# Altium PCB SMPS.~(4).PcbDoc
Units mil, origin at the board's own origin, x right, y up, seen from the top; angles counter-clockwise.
Board outline 3937.01 x 3149.61 mil, 2 copper layers (Top Layer, Bottom Layer); 87 components, 38 nets, 260 pads, 271 vias.
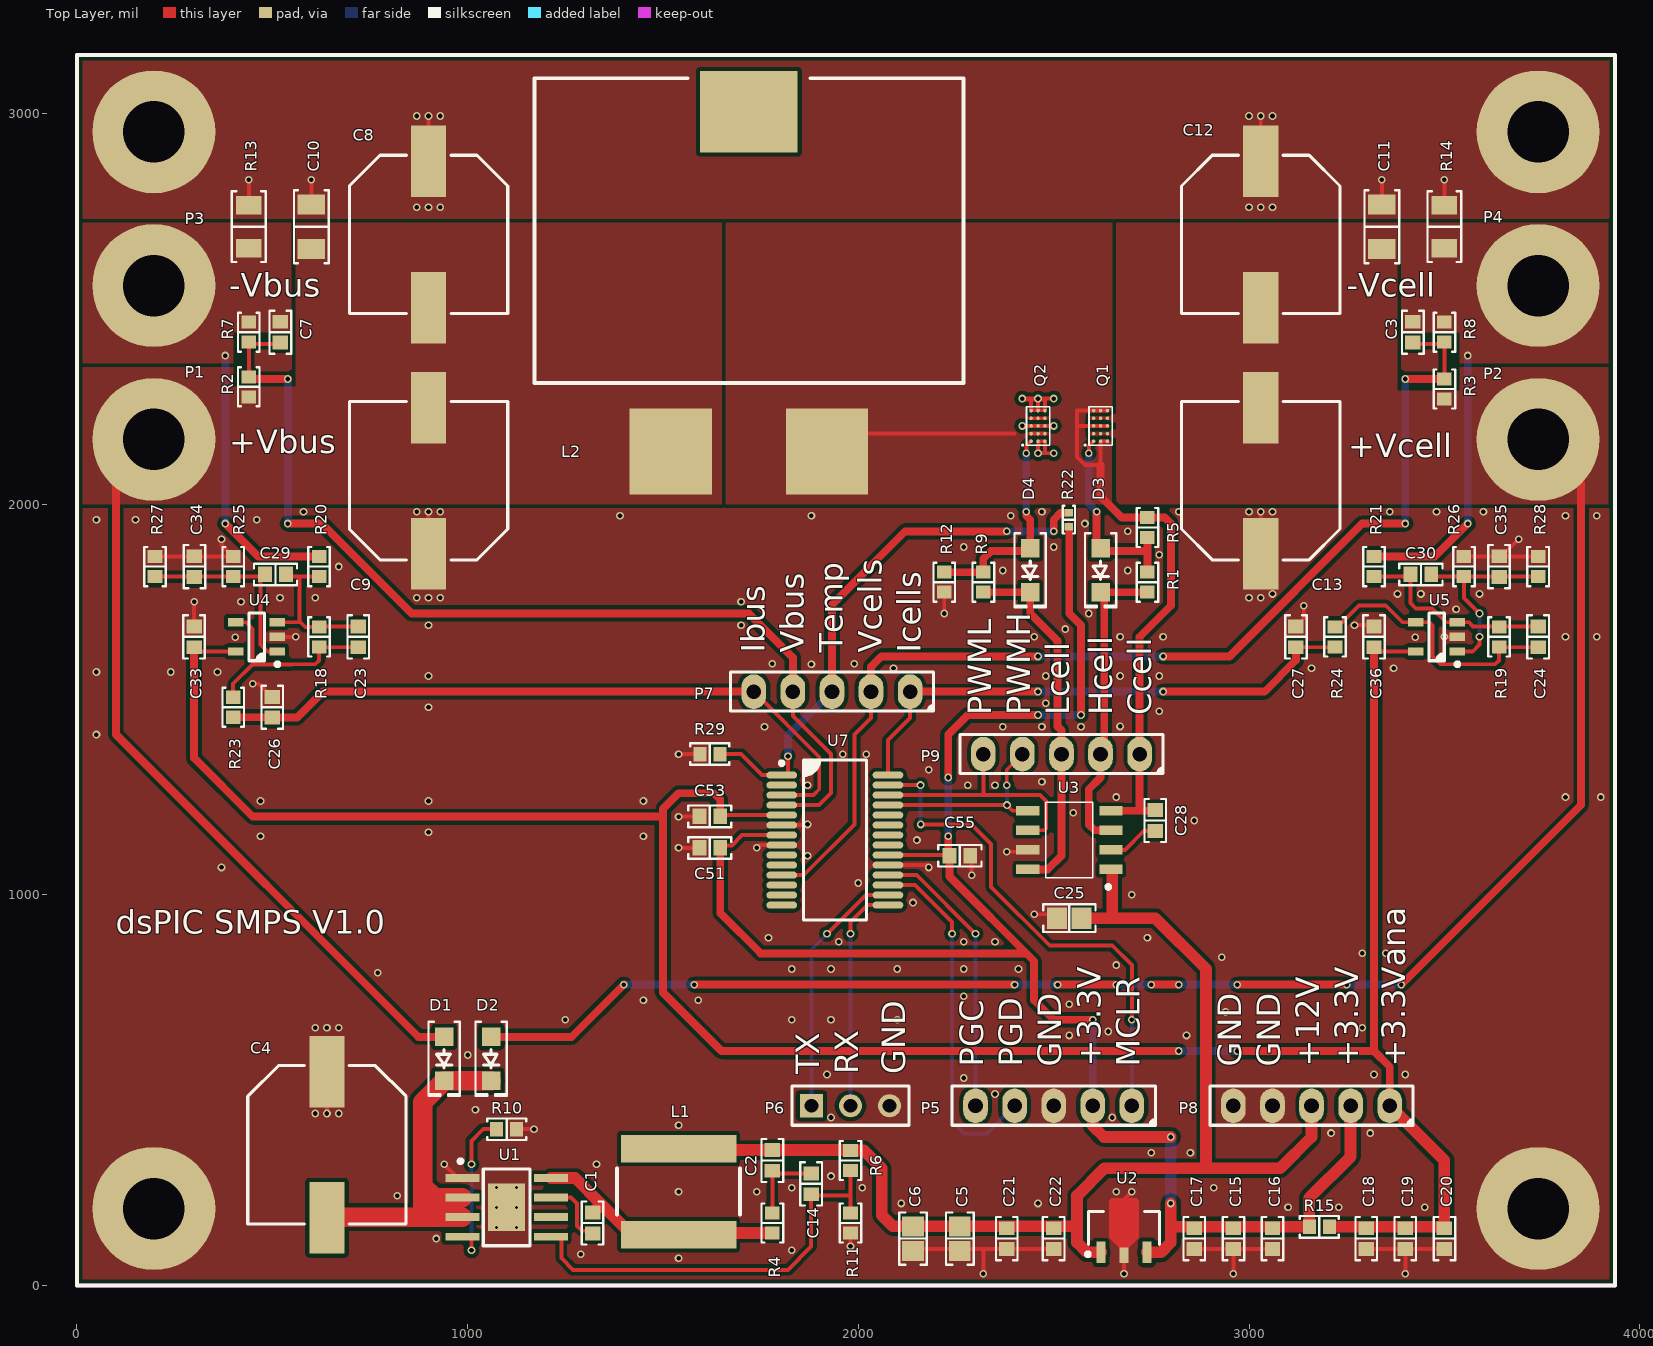
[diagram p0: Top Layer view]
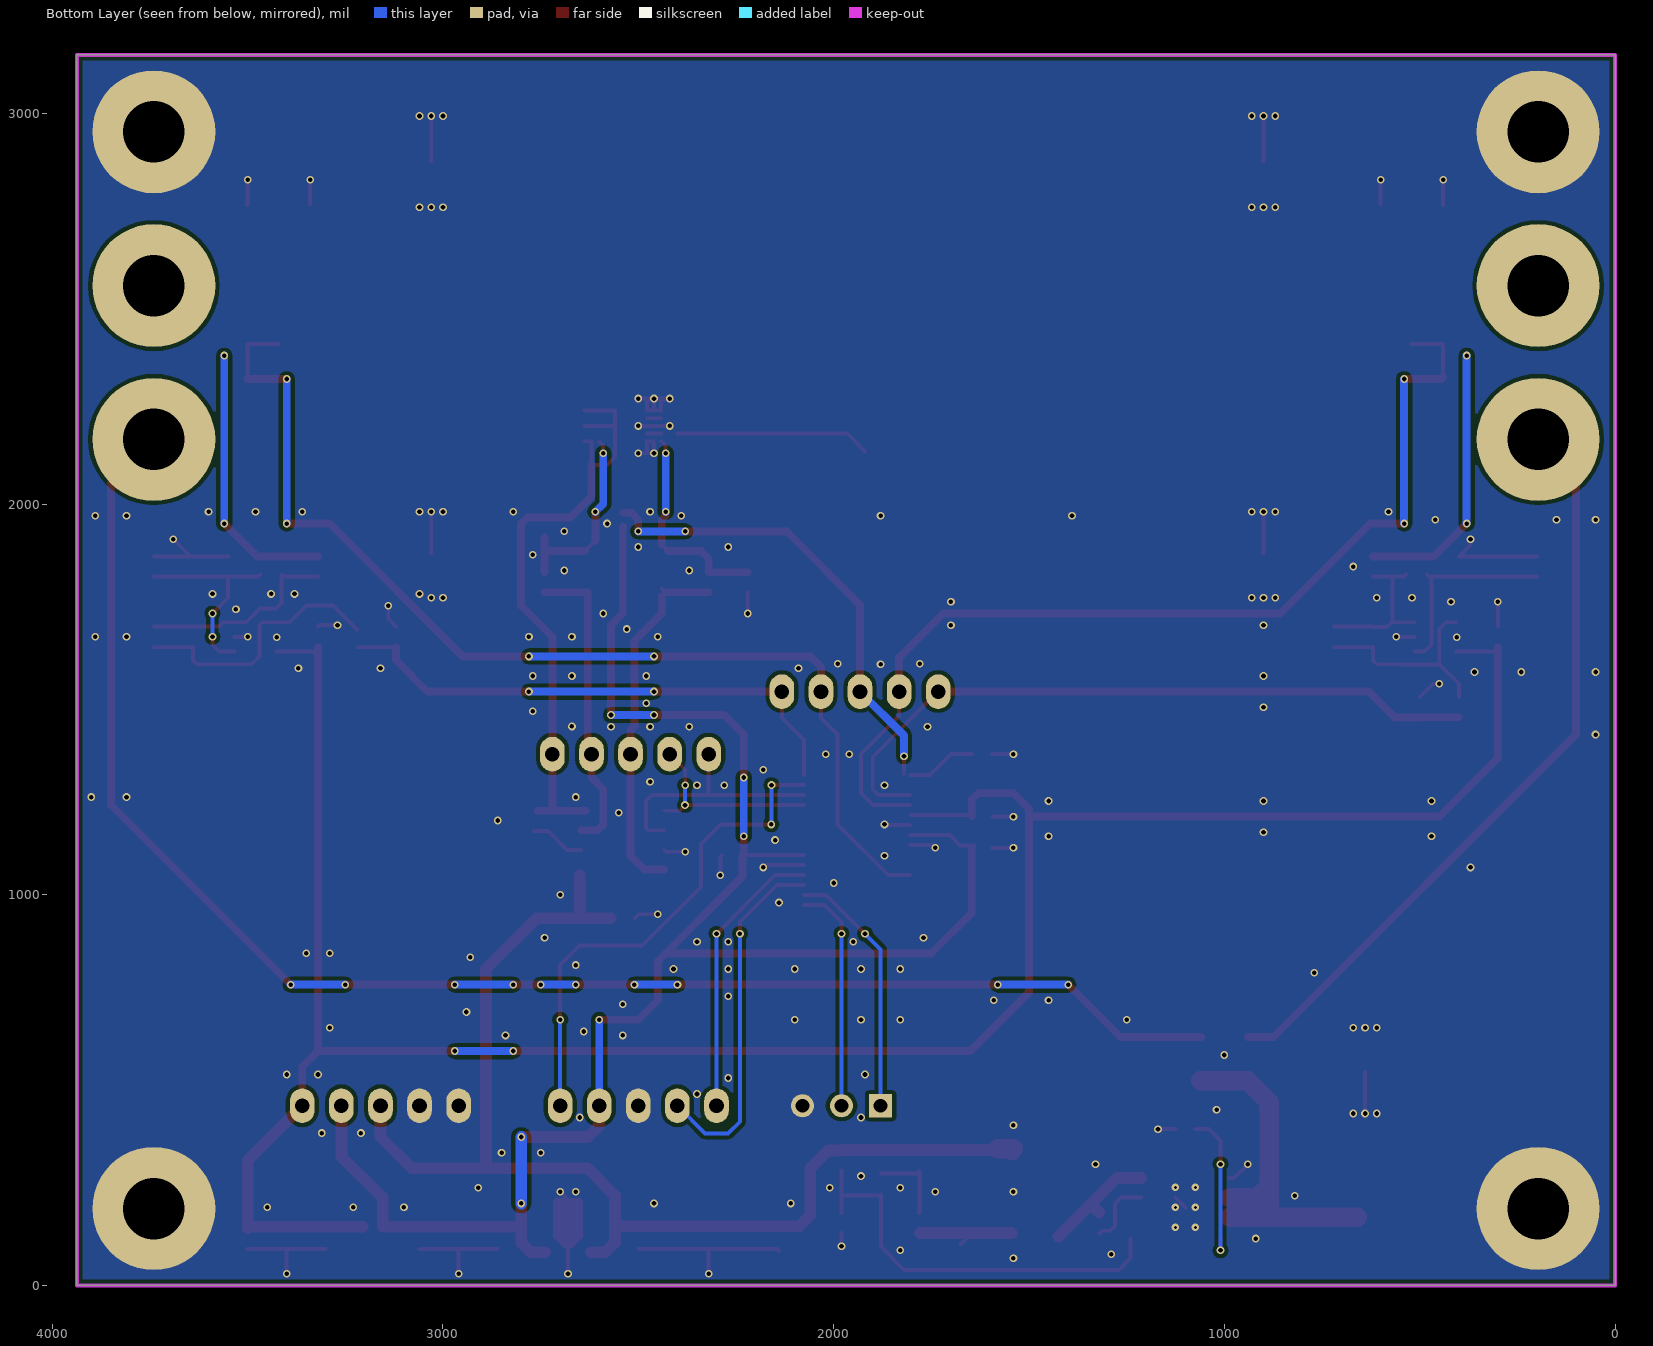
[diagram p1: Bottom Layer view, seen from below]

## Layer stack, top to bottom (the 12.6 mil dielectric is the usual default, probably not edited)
Top Solder: solder mask 0.4, Solder Resist, Dk 3.5
Top Layer: signal copper 1.4
Dielectric 1: dielectric 12.6, FR-4, Dk 4.8
Bottom Layer: signal copper 1.4
Bottom Solder: solder mask 0.4, Solder Resist, Dk 3.5

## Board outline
0,0 0,3149.61 3937.01,3149.61 3937.01,0

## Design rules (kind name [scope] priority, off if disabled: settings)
Clearance [All] p1: gap=10 ignorepadtopadclearanceinfootprint=FALSE except(0: Arc-Hole Track-Hole SMDPad-Hole THPad-Hole Via-Hole Fill-Hole Poly-Hole Region-Hole Text-Hole; 7: SMDPad-SMDPad; 8: Track-SMDPad; 9: Arc-Arc Arc-Track Arc-SMDPad Track-Track; 20: THPad-THPad)
ComponentClearance U1 [InComponent('U1')] p1: gap=20 collisioncheckmode=3 verticalgap=0 showdistances=TRUE
ComponentClearance [All] p2: gap=19.68 collisioncheckmode=3 verticalgap=3.94 showdistances=TRUE
Height [All] p1: minheight=0 maxheight=2000 prefheight=500
HoleSize [All] p1: absolutevalues=TRUE maxlimit=393.7 minlimit=7.87 maxpercent=80.000 minpercent=20.000
MinimumSolderMaskSliver [All] p1: minsoldermaskwidth=1
PlaneClearance [All] p1: clearance=10
PlaneConnect [All] p1: planeconnectstyle=Direct reliefexpansion=20 reliefentries=4 reliefconductorwidth=20 reliefairgap=20
PolygonConnect GND [InNet('GND')] p1: connectstyle=Direct reliefconductorwidth=10 reliefentries=4 polygonreliefangle="90 Angle" airgapwidth=10
PolygonConnect DirectConnect [All] p2: connectstyle=Direct reliefconductorwidth=10 reliefentries=4 polygonreliefangle="90 Angle" airgapwidth=10
RoutingVias [All] p1: holewidth=7.87 width=31.5 viastyle="Through Hole" minholewidth=7.87 minwidth=15.75 maxholewidth=15.75 maxwidth=31.5
SilkToSilkClearance [All] p1: silktosilkclearance=0
SolderMaskExpansion [All] p1: expansion=4
Width [All] p1: maxlimit=500 minlimit=10 preferedwidth=10
23 further rules are at their usual default settings.

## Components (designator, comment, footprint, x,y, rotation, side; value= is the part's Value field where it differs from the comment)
C1 "10nF" C0603 1320,160 r270 top
C2 "1nF" C0603 1780,320 r90 top
C3 "10nF" C0603 3419.28,2440 r270 top
C4 "47µF 80V" "CAP ALUM 10.3MM" 640,360 r270 top
C5 "10µF 16V" C0805 2260,120 r270 top
C6 "10µF 16V" C0805 2140,120 r270 top
C7 "10nF" C0603 520.72,2440 r270 top
C8 "47µF 80V" "CAP ALUM 10.3MM" 900,2690 r270 top
C9 "47µF 80V" "CAP ALUM 10.3MM" 900,2060 r90 top
C10 "1µF 80V" C1206 600,2710 r270 top
C11 "1µF 80V" C1206 3340,2710 r270 top
C12 "47µF 80V" "CAP ALUM 10.3MM" 3030,2690 r270 top
C13 "47µF 80V" "CAP ALUM 10.3MM" 3030,2060 r90 top
C14 "47pF" C0603 1879.28,260 r90 top
C15 "10µF" C0603 2960,120 r270 top
C16 "100nF" C0603 3060,120 r270 top
C17 "10nF" C0603 2860,120 r270 top
C18 "10µF" C0603 3300,120 r270 top
C19 "100nF" C0603 3400,120 r270 top
C20 "10nF" C0603 3500,120 r270 top
C21 "100nF" C0603 2380,120 r270 top
C22 "1µF 16V" C0603 2500,120 r270 top
C23 "22pF" C0603 720,1660 r90 top
C24 "22pF" C0603 3740,1660 r270 top
C25 "10µF 16V" C0805 2540,940 r0 top
C26 "33pF" C0603 500,1480 r270 top
C27 "33pF" C0603 3120,1660 r270 top
C28 "1µF 16V" C0603 2760,1190 r270 top
C29 "22pF" C0603 508.28,1820 r0 top
C30 "22pF" C0603 3440,1820 r180 top
C33 "100nF" C0603 300,1660 r90 top
C34 "22pF" C0603 300.72,1840 r270 top
C35 "22pF" C0603 3640,1840 r270 top
C36 "100nF" C0603 3320,1660 r90 top
C51 "100nF" C0603 1620,1120 r0 top
C53 "100nF" C0603 1620,1200.72 r0 top
C55 "100nF" C0603 2260,1100 r180 top
D1 "DSS120UTR" SOD123F 940,580 r270 top
D2 "DSS120UTR" SOD123F 1060,580 r270 top
D3 "DSS120UTR" SOD123F 2620,1830 r270 top
D4 "DSS120UTR" SOD123F 2440,1830 r270 top
L1 "NR8040T220M" SELF_SMD_8x8 1540,240 r90 top
L2 "PQ2614BHA-150K" SELF_SMD_PQ2617 1720,2700 r0 top
P1 "PTH" HOLE_4#1 196.85,2165.35 r0 top
P2 "PTH" HOLE_4#1 3740.16,2165.35 r0 top
P3 "PTH" HOLE_4#2 196.85,2547.38 r0 top
P4 "PTH" HOLE_4#1 3740.16,2559.06 r0 top
P5 "5x2.54" "SAMTEC SSW-105-03-T-S" 2500,460 r180 top
P6 "3x2.54" HDR1X3 1880,460 r0 top
P7 "5x2.54" "SAMTEC SSW-105-03-T-S" 1932.59,1520 r180 top
P8 "5x2.54" "SAMTEC SSW-105-03-T-S" 3160,460 r180 top
P9 "5x2.54" "SAMTEC SSW-105-03-T-S" 2520,1360 r180 top
Q1 "EPC2045" EPC2045 2620,2200 r90 top
Q2 "EPC2045" EPC2045 2460,2200 r90 top
R1 "5R11" R0603 2740,1800 r90 top
R2 "21.5k 0.1%" R0603 440,2300 r90 top
R3 "21.5k 0.1%" R0603 3500,2294.41 r90 top
R4 "249k" R0603 1780,160 r90 top
R5 "10k" R0603 2740,1940 r90 top
R6 "91k" R0603 1980,320 r270 top
R7 "1k 0.1%" R0603 440,2440 r90 top
R8 "1k 0.1%" R0603 3500,2440 r90 top
R9 "5R11" R0603 2320,1800 r90 top
R10 "30.1k" R0603 1100,400 r0 top
R11 "10k" R0603 1980,160 r270 top
R12 "10k" R0603 2220,1800 r270 top
R13 "5m 1% 1W 50ppm" R1206 440,2710 r270 top
R14 "5m 1% 1W 50ppm" R1206 3500,2710 r90 top
R15 "1R" R0603 3180,150 r180 top
R18 "100k 0.1%" R0603 620,1660 r270 top
R19 "100k 0.1%" R0603 3640,1660 r90 top
R20 "1k 0.1%" R0603 620,1840 r270 top
R21 "1k 0.1%" R0603 3320,1840 r90 top
R22 "10k CTN" "NTC 0402/1005" 2538.65,1960 r270 top
R23 "1k" R0603 400,1480 r270 top
R24 "1k" R0603 3220,1660 r90 top
R25 "1k 0.1%" R0603 400,1840 r270 top
R26 "1k 0.1%" R0603 3550,1840 r90 top
R27 "100k 0.1%" R0603 200,1840 r90 top
R28 "100k 0.1%" R0603 3740,1840 r90 top
R29 "10k" R0603 1620,1360 r180 top
U1 "LM5164" R-PDSO-G8 1100,200 r270 top
U2 "AP7381-33Y-13" "ON SEMI SOT-89 H" 2680,140 r90 top
U3 "MIC4605-1YM" SOIC-8 2540,1140 r180 top
U4 "LMR321G" "TI SOT-23-5 DBV" 460,1660 r180 top
U5 "LMR321G" "TI SOT-23-5 DBV" 3480,1660 r180 top
U7 "dsPIC33CK256MP202" "CYPRESS SSOP-28 210MIL" 1940,1140 r0 top

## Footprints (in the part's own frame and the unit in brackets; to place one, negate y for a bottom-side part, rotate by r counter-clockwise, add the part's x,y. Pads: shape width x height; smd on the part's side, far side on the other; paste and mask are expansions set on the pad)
C0603 [mm] "Chip Capacitor, 2-Leads, Body 1.60x0.80mm, IPC Medium Density"
  rect 0.9x1 smd: 1(-0.675,0) 2(0.675,0)
  silkscreen extent -1.4,-0.7 1.4,0.7, body extent -0.8,-0.41 0.8,0.41, height 0.82
C0805 [mm] "Chip Capacitor, 2-Leads, Body 2.00x1.20mm, IPC Medium Density"
  rect 1.3x1.4 smd: 1(-0.8,0) 2(0.8,0)
  silkscreen extent -1.7,-0.9 1.7,0.9, body extent -1,-0.64 1,0.64, height 1.26
C1206 [mm] "Chip Capacitor, 2-Leads, Body 3.25x1.60mm, IPC Medium Density"
  rect 1.3x1.8 smd: 1(-1.45,0) 2(1.45,0)
  silkscreen extent -2.37,-1.12 2.37,1.12, body extent -1.6,-0.81 1.6,0.81, height 1.62
"CAP ALUM 10.3MM" [mm] "Aluminum Electrolytic Capacitor, Body 10.30x10.30x10.50mm, IPC Low Density"
  rect 4.65x2.3 smd: 1(-4.75,0) 2(4.75,0)
  silkscreen extent -5.15,-5.15 5.15,5.15, body extent -5.8,-5.15 5.8,5.15, height 10.5
"CYPRESS SSOP-28 210MIL" [mm] "SOP, 28-Leads, Body 10.2x5.3mm, Pitch 0.65mm, IPC Medium Density"
  oval 2x0.45 smd: 1(-3.45,4.225) 2(-3.45,3.575) 3(-3.45,2.925) 4(-3.45,2.275) 5(-3.45,1.625) 6(-3.45,0.975) 7(-3.45,0.325) 8(-3.45,-0.325) 9(-3.45,-0.975) 10(-3.45,-1.625) 11(-3.45,-2.275) 12(-3.45,-2.925) 13(-3.45,-3.575) 14(-3.45,-4.225) 15(3.45,-4.225) 16(3.45,-3.575) 17(3.45,-2.925) 18(3.45,-2.275) 19(3.45,-1.625) 20(3.45,-0.975) 21(3.45,-0.325) 22(3.45,0.325) 23(3.45,0.975) 24(3.45,1.625) 25(3.45,2.275) 26(3.45,2.925) 27(3.45,3.575) 28(3.45,4.225)
  silkscreen extent -3.57,-5.2 2.05,5.2, body extent -3.91,-5.1 3.91,5.1, height 1.97
EPC2045 [mm] "EPC2045 GaNFet"
  round 0.23 smd: 1(-1,0.45) 2(-1,-0.45) 2(-1,0) 2(0,0) 2(0,0.45) 2(0,-0.45) 2(1,-0.45) 2(1,0) 2(1,0.45) 3(-0.5,-0.45) 3(-0.5,0) 3(-0.5,0.45) 3(0.5,-0.45) 3(0.5,0) 3(0.5,0.45)
  silkscreen extent -1.3,-0.75 1.25,1.05, body extent -1.25,-0.75 1.25,0.75, height 0.68
HDR1X3 [mm] "Connector; Header; 3 Position"
  rect 1.5x1.5 hole 0.9: 1(0,0)
  round 1.5 hole 0.9: 2(2.54,0) 3(5.08,0)
  silkscreen extent -1.27,-1.27 6.35,1.27
HOLE_4#1 [mm] "Hole for M4 screw"
  round 8 hole 4: 1(0,0)
HOLE_4#2 [mm] "Hole for M4 screw"
  round 8 hole 4: 1(0,0.297)
"NTC 0402/1005" [mm] "Chip Thermistor, 2-Leads, Body 1.00x0.50mm, IPC Medium Density"
  rect 0.5x0.55 smd: 1(-0.45,0) 2(0.45,0)
  silkscreen extent -0.9,-0.4 0.9,0.4, body extent -0.5,-0.26 0.5,0.26, height 0.52
"ON SEMI SOT-89 H" [mm] "SOT89, 3-Leads, Body 4.50x2.50mm, Pitch 1.50mm, Lead Span 3.3mm, IPC Medium Density"
  rect 1.4x0.6 smd: 1(-1.4,1.5) 3(-1.4,-1.5)
  rect 1x0.6 smd: 2(-1.6,0)
  Top Layer region: -1.1,0.3 -0.45,0.95 1.975,0.95 2.1,0.825 2.1,-0.825 1.975,-0.95 -0.45,-0.95 -1.1,-0.3
  silkscreen extent -1.65,-2.3 1.25,2.47, body extent -2.05,-2.25 2.1,2.25, height 1.5
R0603 [mm] "Chip Resistor, 2-Leads, Body 1.60x0.80mm, IPC Medium Density"
  rect 0.85x0.95 smd: 1(-0.65,0) 2(0.65,0)
  silkscreen extent -1.27,-0.7 1.27,0.7, body extent -0.8,-0.4 0.8,0.4, height 0.45
R1206 [mm] "Chip Resistor, 2-Leads, Body 3.13x1.55mm, IPC Medium Density"
  rect 1.2x1.65 smd: 1(-1.4,0) 2(1.4,0)
  silkscreen extent -2.3,-1.1 2.3,1.1, body extent -1.57,-0.8 1.62,0.8, height 0.6
R-PDSO-G8 [mm] "SOIC, 8-Leads, Body 4,90x3,90mm, Pitch 1,27mm, Thermal Pad 3,10x2,40mm, IPC Medium Density"
  rect 0.5x2.2 smd: 1(-1.905,-2.875) 2(-0.635,-2.875) 3(0.635,-2.875) 4(1.905,-2.875) 5(1.905,2.875) 6(0.635,2.875) 7(-0.635,2.875) 8(-1.905,2.875)
  rect 3.1x2.4 smd paste+0: 9(0,0)
  silkscreen extent -3.12,-3.12 2.5,1.52, body extent -2.5,-2 2.5,2, height 1.7
"SAMTEC SSW-105-03-T-S" [mm]
  oval 1.6x2.25 hole 0.95: 1(-5.08,0) 2(-2.54,0) 3(0,0) 4(2.54,0) 5(5.08,0)
  silkscreen extent -6.61,-1.27 6.61,1.27, body extent -6.6,-1.21 6.6,1.21, height 8.51
SELF_SMD_8x8 [mm] "Self SMD 8x8mm"
  rect 1.8x7.5 smd: 1(-2.8,0) 2(2.8,0)
  silkscreen extent -1.5,-4 1.5,4, body extent -4,-4 4,4, height 3
SELF_SMD_PQ2617 [mil] "Bourns shielded power inductor PQ2617"
  rect 210x220 smd: 1(-200,-565) 2(200,-565)
  rect 250x208 smd: 3(0,304)
  silkscreen extent -549,-390 549,390, body extent -549,-433 549,433, height 748
SOD123F [mm] "SODFL, 2-Leads, Body 1.60x3.50mm, IPC Medium Density"
  rect 1.2x1.2 smd: 1(-1.43,0) 2(1.43,0)
  silkscreen extent -2.41,-1.02 2.41,1.02, body extent -1.75,-0.8 1.75,0.8, height 1.1
SOIC-8 [mm] "8-Pin Plastic Narrow Body Small Outline Integrated Circuit 1.27 mm Pitch, IPC Medium Density"
  rect 1.5x0.6 smd: 1(-2.7,1.905) 2(-2.7,0.635) 3(-2.7,-0.635) 4(-2.7,-1.905) 5(2.7,-1.905) 6(2.7,-0.635) 7(2.7,0.635) 8(2.7,1.905)
  silkscreen extent -2.67,-2.45 1.52,3.17, body extent -1.95,-2.45 1.95,2.45, height 1.76
"TI SOT-23-5 DBV" [mm] "SOT23, 5-Leads, Body 2.90x2.80mm, Pitch 0.95mm, IPC Medium Density"
  rect 1x0.55 smd: 1(-1.35,0.95) 2(-1.35,0) 3(-1.35,-0.95) 4(1.35,-0.95) 5(1.35,0.95)
  silkscreen extent -1.48,-1.55 0.5,1.9, body extent -1.44,-1.43 1.39,1.48, height 1.5

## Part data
C1 C2 C3 C4 C5 C6 C7 C8 C9 C10 C11 C12 C13 C14 C15 C16 C17 C18 C19 C20 C21 C22 C23 C24 C25 C26 C27 C28 C29 C30 C33 C34 C35 C36 C51 C53 C55: library part Cap, "Capacitor"
D1 D2 D3 D4: library part "D Schottky", "Schottky Diode"
L1 L2: library part "Inductor Iron", "Magnetic-Core Inductor"
P1 P2 P3 P4: "Plated Trough Hole for screew"
P5 P7 P8 P9: library part "Header 5", "Header, 5-Pin"
P6: library part "Header 3", "Header, 3-Pin"
Q1 Q2: library part MOSFET_N
R1 R2 R3 R4 R5 R6 R7 R8 R9 R10 R11 R12 R13 R14 R15 R18 R19 R20 R21 R23 R24 R25 R26 R27 R28 R29: library part Res2, "Resistor"
R22: library part "Res Varistor", "Varistor (Voltage-Sensitive Resistor)"
U1: "100-V Input, 1-A synchronous buck DC/DC converter with ultra-low IQ"
U2: library part "Volt Reg", "Voltage Regulator"
U3: "85V Half-Bridge MOSFET Driver with Adaptive Dead Time  and Shoot-Through Protection"
U4 U5: library part "AOP - 1"

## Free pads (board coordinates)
  round 314.96 hole 157.48: 1(196.85,196.85) 1(196.85,2952.76) 1(3740.16,196.85) 1(3740.16,2952.76)

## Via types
v1: diameter 19.68, hole 11.81, Top Layer to Bottom Layer, 265 vias
v2: diameter 19.68, hole 7.87, Top Layer to Bottom Layer, 6 vias

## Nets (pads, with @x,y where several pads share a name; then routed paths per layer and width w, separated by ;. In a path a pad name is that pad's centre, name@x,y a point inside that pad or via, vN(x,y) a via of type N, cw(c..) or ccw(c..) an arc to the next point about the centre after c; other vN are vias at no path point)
+3.3V: C15.1 C16.1 C17.1 C51.2 C55.2 P5.2 P8.2 R15.2 R22.2 U2.3 U7.7 U7.20 | length 4669.4
  Top Layer w10: C51.2@1640,1126.57 1676.57,1126.57 1702.8,1152.8 U7.7 ; U7.20 2224.96,1101.61 2233.43,1093.15 C55.2@2240,1086.57
  Top Layer w20: C51.2 1646.57,953.43 1750,850 2430,850 ; v1(2230,1150) 2230,1103.43 C55.2 2233.43,1093.15 2233.43,1046.57 2450,830 2450,730 2500,680 v1(2600,680) ; v1(2230,1300) 2230,1410 2280,1460 v1(2460,1460) ; R22.2 2540,1940.94 2540,1720 2570,1690 v1(2570,1460)
  Top Layer w25: C17.1 C17.1@2863.43,150
  Top Layer w30: P5.2 2600,408.82 2628.82,380 v1(2800,380) ; U2.3 2774.88,84.88 2800,110 v1(2800,210) ; 2804.17,150 2863.43,150 R15.2 3154.41,224.41 3260,330 P8.2
  Bottom Layer w20: v1(2230,1150) v1(2230,1300) ; v1(2460,1460) v1(2570,1460) ; P5.2 v1(2600,680)
  Bottom Layer w30: v1(2800,210) v1(2800,380)
+3.3Vana: C18.1 C19.1 C20.1 C33.1 C36.1 C53.2 P8.1 R15.1 U4.5 U5.5 U7.5 | length 6358.4
  Top Layer w10: C33.1 310.83,1622.6 U4.5 ; C53.2@1640,1213.43 1646.57,1206.85 1649.45,1203.98 U7.5 ; C36.1 3330.83,1622.6 U5.5
  Top Layer w20: C33.1 300,1350 450,1200 1500,1200 ; C53.2 1646.57,1206.85 1646.57,1243.43 1630,1260 1540,1260 1500,1220 1500,750 1650,600 v1(2820,600) ; v1(2970,600) 3320,600 ; C36.1 3320,600 ; P8.1 3360,560 3320,600
  Top Layer w30: R15.1 3496.57,150 C20.1 3500,320 P8.1
  Bottom Layer w20: v1(2820,600) v1(2970,600)
+12V: C2.2 C5.1 C6.1 C21.1 C22.1 C25.2 L1.2 P8.3 R6.1 U2.1 U3.1 | length 3092.4
  Top Layer w30: L1.2@1543.66,346.57 C2.2 R6.1@1980,346.57 ; R6.1 2014.41,345.59 2060,300 2060,180 2088.5,151.5 C6.1 C5.1 2500,151.5 2554.33,151.5 ; C25.2 2760,940 2890,810 2890,300 ; U2.1 2585.12,84.88 2560,110 2560,230 2630,300 3080,300 3160,380 P8.3@3160,420 ; 2650,940 2650,1050
  Top Layer w50: L1.2@1543.66,346.57 L1.2 L1.2@1580,350.24
+Vbus: C8.2 C9.2 C10.2 D1.1 L2.1 P1.1 R2.1 | length 1955.9
  Top Layer w20: P1.1 100,2068.5 100,1410 873.7,636.3 D1.1
+Vcells: C11.2 C12.2 C13.2 D2.1 P2.1 Q1.3 R3.1 | length 4016.8
  Top Layer w20: D2.1 1266.3,636.3 v1(1400,770) ; v1(1580,770) 1900,770 v1(2400,770) ; v1(2510,770) v1(2660,770) ; v1(2750,770) v1(2820,770) ; v1(2970,770) v1(3250,770) ; v1(3390,770) 3850,1230 3850,2055.51 P2.1
  Bottom Layer w20: v1(1400,770) v1(1580,770) ; v1(2400,770) v1(2510,770) ; v1(2660,770) v1(2750,770) ; v1(2820,770) v1(2970,770) ; v1(3250,770) v1(3390,770)
Ccells: C28.1 L2.2 P9.1 Q1.2 Q2.3 R5.2 U3.4 | length 2170.8
  Top Layer w10: L2.2 1965.32,2180.32 2400,2180.32 ; Q2.3@2442.28,2180.32 2460,2180.32 Q2.3@2477.71,2180.32 ; Q2.3@2442.28,2219.69 2460,2219.69 Q2.3@2477.71,2219.69 ; 2620,2142.92 2620,2100 2580,2100 2560,2120 2560,2180 2560,2200 ; 2620,2142.92 2620,2160.63 Q1.2@2637.71,2160.63 ; Q1.2@2637.71,2200 2602.28,2200 2560,2200 ; Q1.2@2637.71,2239.37 2620,2239.37 2602.28,2239.37 2560.63,2239.37 2560,2240 2560,2220 2560,2200
  Top Layer w20: 2620,2100 2620,2020 2674.41,1965.59 R5.2 2784.41,1965.59 2800,1950 2800,1740 2720,1660 P9.1 2720,1215 ; U3.4@2635,1215 U3.4 2720,1215 ; C28.1@2756.67,1215 2720,1215
GND: C4.1 C5.2 C6.2 C8.1 C9.1 C10.1 C11.1 C12.1 C13.1 C15.2 C16.2 C17.2 C18.2 C19.2 C20.2 C21.2 C22.2 C25.1 C26.1 C27.1 C33.2 C34.1 C35.1 C36.2 C51.1 C53.1 C55.1 P5.3 P6.3 P8.4 P8.5 pad.1 Q2.2 R10.2 R11.2 R12.2 R13.1 R14.2 R25.1 R26.2 R27.2 R28.2 R29.2 U1.1 U1.9 U2.2 U3.7 U4.2 U5.2 U7.6 U7.8 U7.19 | length 4074.8
  Top Layer w10: R27.2 R25.1 370,1895.59 v1(370,1910) ; C33.2 v1(300,1750) ; R13.1 v1(440,2830) ; v1(450,1540) 466.57,1540 C26.1 ; U4.2 v1(560,1660) ; C10.1 v1(600,2830) ; v1(640,440) C4.1 ; C9.1 v1(900,1980) ; C8.1 v1(900,2993.15) ; v1(940,310) 975,275 U1.1 ; U1.9 U1.9@1125.59,225.59 ; R10.2 v1(1170,400) ; v1(1540,1120) C51.1 ; v1(1540,1200) 1592.71,1200 C53.1 ; v1(1540,1360) R29.2 ; v1(1740,1120) 1747.2,1127.2 U7.8 ; U7.6 1868.39,1178.39 v1(1870,1180) ; v1(1980,100) R11.2 ; U7.19 2173.98,1076.02 v1(2180,1070) ; C6.2 2144.92,93.43 2323.43,93.43 ; v1(2220,1720) R12.2 ; C55.1 2290,1096.57 v1(2290,1050) ; v1(2320,30) 2320,90 2323.43,93.43 ; v1(2380,1110) 2428.7,1110 U3.7 ; v1(2420,2200) 2460,2200 v1(2500,2200) ; Q2.2@2442.28,2239.37 Q2.2@2442.28,2240 ; v1(2450,950) 2498.5,950 C25.1 ; Q2.2@2460,2239.37 Q2.2@2460,2240 ; 2469.99,2267.71 2422.29,2267.71 v1(2420,2270) 2440,2270 ; Q2.2@2477.71,2239.37 Q2.2@2477.71,2240 ; C22.2 C21.2 2323.43,93.43 ; v1(2500,2130) 2480,2130 ; v1(2500,2270) 2480,2270 ; v1(2680,30) U2.2 2680,220 v1(2700,240) ; C17.2 C15.2 ; v1(2960,30) C15.2 ; C13.1 v1(3030,1980) ; C12.1 v1(3030,2993.15) ; C16.2 C15.2 ; C27.1 3140,1706.57 v1(3140,1740) ; v1(3270,1690) 3316.57,1690 C36.2 ; C18.2 C19.2 ; C11.1 v1(3340,2830) ; v1(3400,30) C19.2 ; v1(3499.69,1660) U5.2 ; C20.2 C19.2 ; R14.2 v1(3500,2830) ; R26.2@3548.28,1865.59 R26.2 C35.1@3645.59,1865.59 ; v1(3690,1910) C35.1@3645.59,1865.59 ; R28.2 C35.1@3645.59,1865.59 ; 2440,2270 v1(2460,2270) ; 2440,2270 2442.28,2267.72 Q2.2@2442.28,2240 ; Q2.2@2442.28,2240 Q2.2@2460,2240 ; Q2.2@2460,2240 v1(2460,2270) ; Q2.2@2460,2240 Q2.2@2477.71,2240 ; v1(2460,2270) 2480,2270 ; Q2.2@2477.71,2240 2477.71,2267.71 2480,2270 ; 2480,2130 v1(2460,2130) 2460,2151.48 2461.28,2152.76 2461.28,2160.63 2477.71,2160.63 2477.71,2132.29 2480,2130
  other v1: 1540,70 1290,80 1830,90 920,120 3100,200 3230,200 3450,200 2110,210 2460,210 820,230 1540,240 1740,240 2660,240 1830,250 2010,250 2910,250 1930,280 1330,310 2750,340 2850,340 3210,390 3310,390 1540,410 1930,430 2650,430 610,440 670,440 1020,450 2350,490 2270,530.87 1920,540 3320,540 3400,540 1000,590 2540,640 2840,640 2640,650 610,660 640,660 670,660 3290,660 1250,680 1830,680 1930,680 2100,680 2940,700 2540,720 1450,730 1590,730 2270,740 770,800 1830,810 1930,810 2100,810 2270,810 2410,810 2660,820 2930,840 3290,850 3350,850 1950,880 2270,880 2350,880 1770,890 2740,890 2140,980 2700,1000 2000,1030 370,1070 1870,1100 2150,1140 470,1150 1450,1150 900,1160 2860,1190 2550,1210 470,1240 900,1240 1450,1240 2660,1250 3810,1250 3900,1250 1870,1280 2280,1280 2350,1280 2470,1289.13 2180,1320 1960,1360 2020,1360 50,1410 1760,1430 2370,1430 2470,1430 2570,1430 2670,1430.87 2770,1470 900,1480 2480,1490 900,1560 2480,1560 2670,1560 2770,1560 50,1570 240,1570 360,1570 2090,1580 3160,1580 3370,1580 1880,1590 1780,1590.87 1990,1590.87 405.45,1659.02 3425.45,1659.02 2450,1660 2670,1660 2780,1660 3810,1660 3890,1660 2530,1680 900,1690 1700,1690 2590,1720 3530,1730.87 420,1750 1700,1750 520,1760 610,1760 870,1760 900,1760 930,1760 3000,1760 3030,1760 3060,1770 3380,1770 3440,1770 3590,1770 2370,1830 2690,1830 670,1840 2770,1870 2270,1890 2500,1890 2690,1930 2580,1950 50,1960 150,1960 460,1960 1390,1970 1880,1970 2390,1970 3810,1970 3890,1970 580,1980 870,1980 930,1980 2470,1980 2820,1980 3000,1980 3060,1980 3360,1980 3480,1980 3600,1980 870,2760 900,2760 930,2760 3000,2760 3030,2760 3060,2760 870,2993.15 930,2993.15 3000,2993.15 3060,2993.15
  other v2: 1074.41,148.82 1125.59,148.82 1074.41,200 1125.59,200 1074.41,251.18 1125.59,251.18
Hcells: D3.2 P9.2 R1.1 U3.3 | length 783.9
  Top Layer w20: U3.3 2605,1165 2590,1180 2590,1270 2620,1300 P9.2 2629.29,1369.29 2629.29,1774.41 R1.1
Ibus_sense: C26.2 P7.5 R23.2 U7.3 | length 1781.9
  Top Layer w10: C26.2@499.02,1454.41 C26.2 ; P7.5 1900,1352.59 1900,1270 1885.16,1255.16 U7.3
  Top Layer w20: R23.2 C26.2@499.02,1454.41 ; C26.2 563.43,1453.43 630,1520 P7.5
Icells_sense: C27.2 P7.1 R24.1 U7.28 | length 1390.2
  Top Layer w10: U7.28 2075.83,1395.83 2132.59,1452.59 P7.1 ; C27.2 R24.1@3219.02,1633.43
  Top Layer w20: P7.1 v1(2460,1520) ; v1(2780,1520) 3040,1520 3120,1600 C27.2
  Bottom Layer w20: v1(2460,1520) v1(2780,1520)
Lcells: D4.2 P9.3 R9.1 U3.8 | length 921.5
  Top Layer w10: D4.2@2430.71,1774.41 D4.2@2440,1783.7
  Top Layer w20: R9.1 D4.2@2430.71,1774.41 ; U3.8 2485,1065 2520,1100 P9.3 2520,1420.87 2510,1430.87 2510,1650 2440.01,1719.99 D4.2@2440.01,1763.71
M\C\L\R\: P5.1 U7.27 | length 1298
  Top Layer w10: U7.27 v1(2159.25,1280.75) ; v1(2160,1180) 2290,1180 2340,1130 2340,1020 2490,870 2650,870 2700,820 v1(2700,680)
  Bottom Layer w10: v1(2159.25,1280.75) 2159.25,1180.75 v1(2160,1180) ; P5.1 v1(2700,680)
NetC1_1: C1.1 L1.1 R4.1 U1.8 | length 691.8
  Top Layer w10: L1.1 1650.24,129.76 L1.1@1675,105
  Top Layer w20: L1.1 L1.1@1544.65,134.41
  Top Layer w30: U1.8 1275,275 1341.71,208.29 ; C1.1 1341.71,208.29 ; L1.1@1425,125 1341.71,208.29 ; L1.1@1544.65,134.41 R4.1
NetC1_2: C1.2 U1.7 | length 178.5
  Top Layer w10: U1.7 1265,225 1280,210 1280,152.44 1292.44,140 1313.43,140 C1.2
NetC2_1: C2.1 C14.2 R4.2 | length 210
  Top Layer w10: R4.2 C2.1 1786.85,286.57 C14.2
NetC4_2: C4.2 D1.2 D2.2 U1.2 U1.3 | length 932.5
  Top Layer w50: C4.2@660,175 885,175 ; U1.3 885,175 ; U1.2 915,225 885,255 ; D2.2 D1.2 885,468.7 885,255 ; 885,175 885,255
NetC14_1: C14.1 R6.2 R11.1 U1.5 | length 1071.4
  Top Layer w10: U1.5@1240,120 1240,70 1270,40 1820,40 1879.28,99.28 C14.1 1882.71,230 1980,230 ; R11.1 1980,230 ; R6.2 1980,230
NetC23_1: C23.1 R18.2 R23.1 U4.4 | length 554
  Top Layer w10: R23.1 400,1540 449.13,1589.13 ; U4.4 432.6,1697.4 450,1680 450,1589.13 549.13,1589.13 550,1590 610,1590 620,1600 R18.2@620,1633.43 ; R18.2 R18.2@620,1633.43 ; C23.1 R18.2@620,1633.43
NetC23_2: C23.2 C29.2 R18.1 R20.2 U4.3 | length 417.7
  Top Layer w10: U4.3 572.6,1697.4 ; C29.2 540.44,1814.41 570,1814.41 ; R20.2 570,1814.41 ; C23.2 620.98,1686.57 R18.1 584.41,1685.59 572.6,1697.4 ; 570,1814.41 570,1700 572.6,1697.4
NetC24_1: C24.1 C30.2 R19.2 R21.1 U5.3 | length 522
  Top Layer w10: R21.1 3407.83,1814.41 C30.2 3413.43,1746.57 3426.85,1733.15 3467.87,1733.15 3503.62,1697.4 U5.3 3562.6,1697.4 3573.43,1686.57 R19.2@3640.98,1686.57 ; R19.2 R19.2@3640.98,1686.57 ; C24.1 R19.2@3640.98,1686.57
NetC24_2: C24.2 R19.1 R24.2 U5.4 | length 693.2
  Top Layer w10: R24.2@3220,1678.7 3281.3,1740 3350,1740 3392.6,1697.4 3462.28,1697.4 3470,1689.69 3470,1610 3490,1590 3540,1590 3630,1590 3640,1600 R19.1 3640.98,1633.43 C24.2
NetC28_2: C28.2 U3.2 | length 140.9
  Top Layer w10: U3.2 2682.11,1115 2730.53,1163.43 C28.2@2767.11,1163.43
NetC29_1: C29.1 C34.2 R25.2 R27.1 U4.1 | length 511.3
  Top Layer w10: R27.1 C29.1@476.11,1814.41 ; C29.1 C29.1@476.11,1814.41 ; U4.1 487.4,1622.6 470,1640 470,1808.3 C29.1@476.11,1814.41
NetC30_1: C30.1 C35.2 R26.1 R28.1 U5.1 | length 530.8
  Top Layer w10: C30.1 3472.17,1814.41 R26.1 ; U5.1 3572.6,1622.6 3590,1640 v1(3590,1660) ; v1(3590,1720) 3550,1760 R26.1 ; R28.1 R26.1
  Bottom Layer w10: v1(3590,1660) v1(3590,1720)
NetD3_1: D3.1 Q1.1 R1.2 R5.1 | length 494.3
  Top Layer w10: v1(2590,2130) 2590,2150 Q1.1@2598.9,2158.9 ; D3.1@2610,1906.3 D3.1@2636.3,1880
  Top Layer w20: D3.1@2610,1906.3 v1(2610,1980) ; D3.1@2636.3,1880 2740,1880 ; R1.2 2740,1880 ; R5.1 2740,1880
  Bottom Layer w20: v1(2590,2130) 2590,2000 v1(2610,1980)
NetD4_1: D4.1 Q2.1 R9.2 R12.1 | length 544
  Top Layer w10: D4.1@2423.7,1880 D4.1@2440,1896.3 ; v1(2430,2130) 2430,2150 2440.63,2160.63 Q2.1
  Top Layer w20: R12.1 R9.2 2320,1860 2340,1880 D4.1@2423.7,1880 ; v1(2430,1980) 2430,1970 2440,1960 D4.1@2440,1896.3
  Bottom Layer w20: v1(2430,1980) v1(2430,2130)
NetR10_1: R10.1 U1.4 | length 386.8
  Top Layer w10: v1(1010,90) U1.4@1010,120 ; v1(1010,310) 1010,370 1040,400 R10.1
  Bottom Layer w10: v1(1010,90) v1(1010,310)
PGC: P5.5 U7.18 | length 754.8
  Top Layer w10: U7.18 2149.57,1050.43 v1(2300,900) ; P5.5@2280,480 P5.5
  Bottom Layer w10: P5.5 v1(2300,900)
PGD: P5.4 U7.17 | length 916.1
  Top Layer w10: U7.17 2145.16,1024.84 2240,930 v1(2240,900)
  Bottom Layer w10: v1(2240,900) 2240,419.13 2270,389.13 2329.13,389.13 P5.4
PWMH: P9.4 U3.5 U7.25 | length 510.5
  Top Layer w10: U7.25 v1(2380.43,1229.57) 2395,1215 U3.5 ; v1(2380,1280) 2380,1320 P9.4
  Bottom Layer w10: v1(2380.43,1229.57) v1@2380.43,1279.57
PWML: P9.5 U3.6 U7.26 | length 633.7
  Top Layer w10: U7.26 2320,1255.16 ; P9.5 2320,1255.16 ; U3.6 2475,1165 2480,1170 2480,1240 2464.84,1255.16 2320,1255.16
Rbus: C7.1 P3.1 R7.2 R13.2 R20.1 | length 705
  Top Layer w20: v1(380,1950) 464.41,1865.59 R20.1
  Bottom Layer w20: v1(380,1950) v1(380,2380)
Rcells: C3.1 P4.1 R8.2 R14.1 R21.2 | length 705
  Top Layer w20: R21.2 3475.59,1865.59 v1(3560,1950)
  Bottom Layer w20: v1(3560,1950) v1(3560,2380)
RX: P6.2 U7.15 | length 583.9
  Top Layer w10: v1(1980,900) 1980,930 2023.66,973.66 U7.15
  Bottom Layer w10: P6.2 v1(1980,900)
Temp: P7.3 R22.1 R29.1 U7.1 | length 1381.3
  Top Layer w10: R29.1 1700,1360 1753.66,1306.34 U7.1 ; U7.1@1820,1310 v1(1820,1354.57)
  Top Layer w20: P7.3 1932.59,1742.59 2120,1930 v1(2380,1930) ; v1@2500.51,1930 2500,1930.51 2500,1960 2517.72,1977.72 R22.1
  Bottom Layer w20: v1(1820,1354.57) 1820,1407.41 P7.3 ; v1(2380,1930) v1(2500,1930)
TX: P6.1 U7.16 | length 653.5
  Top Layer w10: v1(1920,900) 2019.25,999.25 U7.16
  Bottom Layer w10: P6.1 1880,860 v1(1920,900)
Vbus_sense: C7.2 P7.4 R2.2 R7.1 U7.4 | length 2598.1
  Top Layer w10: R2.2 440,2410 C7.2@520.72,2410 ; U7.4 1899.57,1229.57 1930,1260 1930,1360 1832.59,1457.41 P7.4
  Top Layer w20: R2.2 445.59,2320 v1(540,2320) ; v1(540,1950) 626.85,1950 856.85,1720 1720,1720 1832.59,1607.41 P7.4
  Bottom Layer w20: v1(540,1950) v1(540,2320)
Vcells_sense: C3.2 P7.2 R3.2 R8.1 U7.11 | length 2822.7
  Top Layer w10: U7.11 1860.43,1050.43 1990,1180 1990,1410 2032.59,1452.59 P7.2 ; C3.2@3419.28,2410 3501.5,2410 3500,2408.5 R3.2
  Top Layer w20: P7.2 2032.59,1583.45 2059.13,1610 v1(2460,1610) ; v1(2780,1610) 2950,1610 3290,1950 v1(3400,1950) ; v1(3400,2320) R3.2
  Bottom Layer w20: v1(2460,1610) v1(2780,1610) ; v1(3400,1950) v1(3400,2320)
pads on no net: L2.3 U1.6 U7.2 U7.9 U7.10 U7.12 U7.13 U7.14 U7.21 U7.22 U7.23 U7.24

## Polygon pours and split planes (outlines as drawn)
Ccells on Top Layer "Ccells-top" (solid, pour order 79): 1660,2000 2648.5,2000 2648.5,2170 2648.5,2190 2580,2190 2580,2210 2649.52,2210 2649.52,2229.22 2650,2229.69 2650,2270 2650,2420 2650,2720 1660,2720
Rcells on Top Layer "Rcells-top" (solid, pour order 77): 3920,2360 3540,2360 3540,2440 3391.72,2440 3390,2441.72 3390,2720 3920,2720
+Vcells on Top Layer "Vcells-top" (solid, pour order 75): 2660,2210 2590.47,2210 2590.47,2230 2660,2230 2660,2720 3380,2720 3380,2290 3540,2290 3540,2350 3920,2350 3920,2000 2660,2000 2660,2170 2590.47,2170 2590.47,2190 2660,2190
Rbus on Top Layer "Rbus-top" (solid, pour order 73): 10,2440 10,2434.71 10,2360 400,2360 400,2440 548.28,2440 548.28,2698.28 548.28,2720 10,2720
+Vbus on Top Layer "Vbus-top" (solid, pour order 72): 400,2300 400,2350 10,2350 10,2000 1650,2000 1650,2720 560,2720 560,2300
GND on Bottom Layer "GND_bottom" (solid, pour order 83): 0,0 3937.01,0 3937.01,3149.61 0,3149.61
GND on Top Layer "GND_top" (solid, pour order 81): 0,0 3937.01,0 3937.01,3149.61 0,3149.61

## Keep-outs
Keep-Out Layer:
  the board outline again, w10

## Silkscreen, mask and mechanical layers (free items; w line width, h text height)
Top Overlay:
  the board outline again, w10
  text "-Vbus" at 390,2530 h60
  text "-Vcell" at 3250.47,2530 h60
  text "+Vbus" at 390,2130 h60
  text "+Vcell" at 3254.41,2120 h60
  text "Ibus" at 1760,1620 h60 r90
  text "Vbus" at 1860,1620 h60 r90
  text "Temp" at 1960,1620 h60 r90
  text "Vcells" at 2060,1620 h60 r90
  text "Icells" at 2160,1620 h60 r90
  text "PWML" at 2340,1460 h60 r90
  text "PWMH" at 2440,1460 h60 r90
  text "Lcell" at 2540,1460 h60 r90
  text "Hcell" at 2650,1460 h60 r90
  text "Ccell" at 2750,1460 h60 r90
  text "dsPIC SMPS V1.0" at 100,900 h60
  text "PGC" at 2320,560 h60 r90
  text "PGD" at 2420,560 h60 r90
  text "GND" at 2520,560 h60 r90
  text "+3.3V" at 2620,560 h60 r90
  text "MCLR" at 2720,560 h60 r90
  text "GND" at 2980,560 h60 r90
  text "GND" at 3080,560 h60 r90
  text "+12V" at 3180,560 h60 r90
  text "+3.3V" at 3280,560 h60 r90
  text "+3.3Vana" at 3400,560 h60 r90
  text "TX" at 1900,540 h60 r90
  text "RX" at 2000,540 h60 r90
  text "GND" at 2120,540 h60 r90
Drill Drawing:
  the board outline again, w10

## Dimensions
0,-39.37 to 3937.01,-78.74 on Mechanical 2
-39.37,0 to -39.37,3149.61 on Mechanical 2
